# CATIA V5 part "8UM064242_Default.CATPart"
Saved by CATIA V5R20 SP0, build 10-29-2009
Part number: 8UM064242_Default
Revision: ANY
Definition: UNKNOWN
Nomenclature: 8UM064242_Default
Source: Unknown
Bounding box of the stored display mesh (mm): x -53.308 to -11.308, y 0 to 28, z -41.652 to 0.348
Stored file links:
  C:\Users\Utente\Desktop\IO LAVORO\3D X SITO CF\X SITO\3D files UM\UM064242 PRODUCT\8UM064242_Default.CATPart
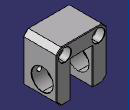
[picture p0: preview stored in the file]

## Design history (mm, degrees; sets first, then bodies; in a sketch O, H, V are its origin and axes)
Body1 "Taladro roscado M51" (main body)
  Solid1: solid without history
